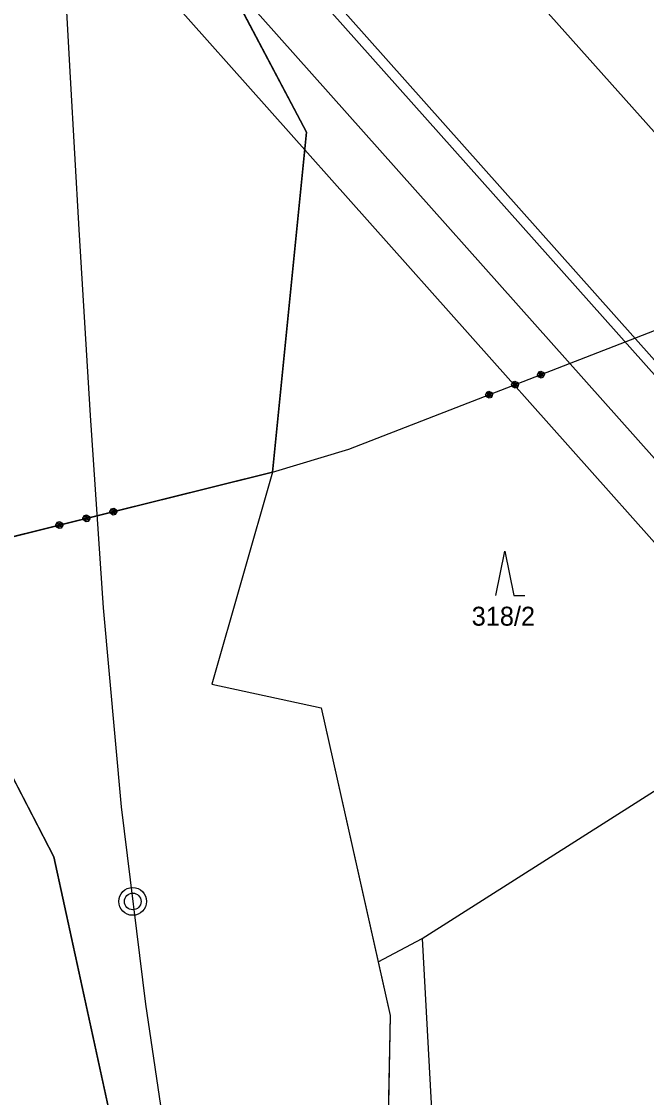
# Model space of a CAD drawing. Extents: x -866656 to -858817, y -1041816 to -1038653.
# Drawn here: x -865011.3 to -864955.2, y -1040747.1 to -1040650.5 of the extents above; entities that cross this region are included whole.
import ezdxf

# ---------------------------------------------------------------- set-up
doc = ezdxf.new("R2010")
doc.units = 0
for name, color, linetype in [('SZDC', 7, 'Continuous'), ('tisk ramy', 7, 'Continuous'), ('Vrstva 1', 7, 'Continuous'), ('Vrstva 3', 7, 'Continuous'), ('Vrstva 53', 7, 'Continuous'), ('Vrstva 7', 7, 'Continuous')]:
    doc.layers.add(name, color=color, linetype=linetype)

msp = doc.modelspace()

# ---------------------------------------------------------------- linework, layer by layer
at = {"layer": 'SZDC'}
for points in [[(-865001.396, -1040539.962), (-864993.688, -1040579.203), (-864996.501, -1040608.857), (-865002.06, -1040629.39), (-864985.688, -1040660.423), (-864988.738, -1040690.926), (-865021.96, -1040699.19), (-865027.168, -1040689.139), (-865033.06, -1040677.767), (-865026.63, -1040662), (-865024.654, -1040657.157), (-865013.46, -1040629.71), (-865015.641, -1040623.593), (-865021.207, -1040607.979), (-865022.973, -1040591.404), (-865024.6, -1040576.14), (-865021.44, -1040540.27)], [(-864972.331, -1040948.544), (-864965.463, -1040904.572), (-864985, -1040866.09), (-864987.66, -1040820.56), (-865008.38, -1040725.45), (-865021.96, -1040699.19), (-864988.738, -1040690.926), (-864994.191, -1040709.967), (-864984.36, -1040712.09), (-864979.245, -1040734.883), (-864978.161, -1040739.712), (-864978.755, -1040767.78), (-864956.64, -1040823.78), (-864971.416, -1040839.192), (-864953.61, -1040862.72), (-864958.96, -1040864.07), (-864953.81, -1040886.99), (-864953.18, -1040911.04), (-864934.86, -1040933.14), (-864931.196, -1040972.036)]]:
    msp.add_lwpolyline(points, dxfattribs=at)
at = {"layer": 'tisk ramy'}
for p, q in [((-865006.182, -1040602.312), (-864942.746, -1040673.565)), ((-864896.72, -1040747.042), (-865017.586, -1040611.282)), ((-865016.338, -1040611.354), (-864952.902, -1040682.607))]:
    msp.add_line(p, q, dxfattribs=at)
for points in [[(-865732.632, -1039823.163), (-864894.802, -1040764.235), (-864672.984, -1040566.751), (-865510.814, -1039625.68)], [(-865511.224, -1039632.739), (-864680.043, -1040566.341), (-864894.393, -1040757.175), (-865725.573, -1039823.573)]]:
    msp.add_lwpolyline(points, close=True, dxfattribs=at)
at = {"layer": 'Vrstva 1'}
for p, q in [((-864985.688, -1040660.423), (-865002.06, -1040629.39)), ((-864988.738, -1040690.926), (-864985.688, -1040660.423)), ((-864988.738, -1040690.926), (-864994.191, -1040709.967)), ((-864968.68, -1040702.01), (-864967.88, -1040698.01)), ((-864967.88, -1040698.01), (-864967.08, -1040702.01)), ((-865021.96, -1040699.19), (-865008.38, -1040725.45)), ((-864967.08, -1040702.01), (-864966.08, -1040702.01)), ((-864994.191, -1040709.967), (-864984.36, -1040712.09)), ((-864984.36, -1040712.09), (-864978.161, -1040739.712)), ((-864975.3, -1040732.8), (-864945.5, -1040713.85)), ((-865008.38, -1040725.45), (-864987.66, -1040820.56)), ((-864979.245, -1040734.883), (-864975.3, -1040732.8)), ((-864975.3, -1040732.8), (-864973.89, -1040758.79)), ((-864978.161, -1040739.712), (-864978.755, -1040767.78))]:
    msp.add_line(p, q, dxfattribs=at)
for points in [[(-865018.381, -1040455.781), (-865018.108, -1040460.39), (-865017.217, -1040475.753), (-865015.827, -1040499.871), (-865013.524, -1040539.806), (-865010.906, -1040584.551), (-865008.335, -1040629.672), (-865006.896, -1040655.504), (-865006.134, -1040669.149), (-865005.12, -1040685.843), (-865003.949, -1040703.111)], [(-865003.949, -1040703.111), (-865002.333, -1040720.961), (-865000.151, -1040738.69), (-864998.444, -1040750.203), (-864996.845, -1040759.743), (-864995.021, -1040769.634), (-864993.251, -1040778.494), (-864990.899, -1040789.361), (-864988.534, -1040799.208), (-864982.898, -1040820.532)]]:
    msp.add_lwpolyline(points, dxfattribs=at)
at = {"layer": 'Vrstva 3'}
for p, q in [((-864981.88, -1040688.87), (-864951.85, -1040677.21)), ((-864981.88, -1040688.87), (-864951.85, -1040677.21)), ((-864964.943, -1040682.186), (-864964.829, -1040681.927)), ((-864964.943, -1040682.186), (-864964.829, -1040681.927)), ((-864964.829, -1040681.927), (-864964.643, -1040681.855)), ((-864964.829, -1040681.927), (-864964.643, -1040681.855)), ((-864964.793, -1040682.021), (-864964.606, -1040681.948)), ((-864964.793, -1040682.021), (-864964.606, -1040681.948)), ((-864964.648, -1040682.393), (-864964.793, -1040682.021)), ((-864964.648, -1040682.393), (-864964.793, -1040682.021)), ((-864964.7, -1040681.984), (-864964.555, -1040682.357)), ((-864964.7, -1040681.984), (-864964.555, -1040682.357)), ((-864964.643, -1040681.855), (-864964.384, -1040681.969)), ((-864964.643, -1040681.855), (-864964.384, -1040681.969)), ((-864964.606, -1040681.948), (-864964.462, -1040682.321)), ((-864964.606, -1040681.948), (-864964.462, -1040682.321)), ((-864964.405, -1040682.192), (-864964.477, -1040682.005)), ((-864964.405, -1040682.192), (-864964.477, -1040682.005)), ((-864964.384, -1040681.969), (-864964.311, -1040682.155)), ((-864964.384, -1040681.969), (-864964.311, -1040682.155)), ((-864967.274, -1040683.091), (-864967.16, -1040682.832)), ((-864967.274, -1040683.091), (-864967.16, -1040682.832)), ((-864967.201, -1040683.278), (-864967.274, -1040683.091)), ((-864967.201, -1040683.278), (-864967.274, -1040683.091)), ((-864967.18, -1040683.055), (-864967.108, -1040683.241)), ((-864967.18, -1040683.055), (-864967.108, -1040683.241)), ((-864967.16, -1040682.832), (-864966.973, -1040682.76)), ((-864967.16, -1040682.832), (-864966.973, -1040682.76)), ((-864967.123, -1040682.925), (-864966.937, -1040682.853)), ((-864967.123, -1040682.925), (-864966.937, -1040682.853)), ((-864966.979, -1040683.298), (-864967.123, -1040682.925)), ((-864966.979, -1040683.298), (-864967.123, -1040682.925)), ((-864967.03, -1040682.889), (-864966.885, -1040683.262)), ((-864967.03, -1040682.889), (-864966.885, -1040683.262)), ((-864966.973, -1040682.76), (-864966.714, -1040682.874)), ((-864966.973, -1040682.76), (-864966.714, -1040682.874)), ((-864966.937, -1040682.853), (-864966.792, -1040683.226)), ((-864966.937, -1040682.853), (-864966.792, -1040683.226)), ((-864966.735, -1040683.097), (-864966.807, -1040682.91)), ((-864966.735, -1040683.097), (-864966.807, -1040682.91)), ((-864966.642, -1040683.06), (-864966.756, -1040683.319)), ((-864966.642, -1040683.06), (-864966.756, -1040683.319)), ((-864966.714, -1040682.874), (-864966.642, -1040683.06)), ((-864966.714, -1040682.874), (-864966.642, -1040683.06)), ((-864964.871, -1040682.373), (-864964.943, -1040682.186)), ((-864964.871, -1040682.373), (-864964.943, -1040682.186)), ((-864964.612, -1040682.487), (-864964.871, -1040682.373)), ((-864964.612, -1040682.487), (-864964.871, -1040682.373)), ((-864964.85, -1040682.15), (-864964.777, -1040682.336)), ((-864964.85, -1040682.15), (-864964.777, -1040682.336)), ((-864964.777, -1040682.336), (-864964.648, -1040682.393)), ((-864964.777, -1040682.336), (-864964.648, -1040682.393)), ((-864964.425, -1040682.414), (-864964.612, -1040682.487)), ((-864964.425, -1040682.414), (-864964.612, -1040682.487)), ((-864964.462, -1040682.321), (-864964.405, -1040682.192)), ((-864964.462, -1040682.321), (-864964.405, -1040682.192)), ((-864964.311, -1040682.155), (-864964.425, -1040682.414)), ((-864964.311, -1040682.155), (-864964.425, -1040682.414)), ((-864969.604, -1040683.996), (-864969.49, -1040683.737)), ((-864969.604, -1040683.996), (-864969.49, -1040683.737)), ((-864969.532, -1040684.182), (-864969.604, -1040683.996)), ((-864969.532, -1040684.182), (-864969.604, -1040683.996)), ((-864969.511, -1040683.96), (-864969.438, -1040684.146)), ((-864969.511, -1040683.96), (-864969.438, -1040684.146)), ((-864969.49, -1040683.737), (-864969.304, -1040683.665)), ((-864969.49, -1040683.737), (-864969.304, -1040683.665)), ((-864969.454, -1040683.83), (-864969.267, -1040683.758)), ((-864969.454, -1040683.83), (-864969.267, -1040683.758)), ((-864969.309, -1040684.203), (-864969.454, -1040683.83)), ((-864969.309, -1040684.203), (-864969.454, -1040683.83)), ((-864969.361, -1040683.794), (-864969.216, -1040684.167)), ((-864969.361, -1040683.794), (-864969.216, -1040684.167)), ((-864969.304, -1040683.665), (-864969.045, -1040683.779)), ((-864969.304, -1040683.665), (-864969.045, -1040683.779)), ((-864969.267, -1040683.758), (-864969.123, -1040684.131)), ((-864969.267, -1040683.758), (-864969.123, -1040684.131)), ((-864969.066, -1040684.001), (-864969.138, -1040683.815)), ((-864969.066, -1040684.001), (-864969.138, -1040683.815)), ((-864969.123, -1040684.131), (-864969.066, -1040684.001)), ((-864969.123, -1040684.131), (-864969.066, -1040684.001)), ((-864968.972, -1040683.965), (-864969.086, -1040684.224)), ((-864968.972, -1040683.965), (-864969.086, -1040684.224)), ((-864969.045, -1040683.779), (-864968.972, -1040683.965)), ((-864969.045, -1040683.779), (-864968.972, -1040683.965)), ((-864966.942, -1040683.392), (-864967.201, -1040683.278)), ((-864966.942, -1040683.392), (-864967.201, -1040683.278)), ((-864967.108, -1040683.241), (-864966.979, -1040683.298)), ((-864967.108, -1040683.241), (-864966.979, -1040683.298)), ((-864966.756, -1040683.319), (-864966.942, -1040683.392)), ((-864966.756, -1040683.319), (-864966.942, -1040683.392)), ((-864966.792, -1040683.226), (-864966.735, -1040683.097)), ((-864966.792, -1040683.226), (-864966.735, -1040683.097)), ((-864969.273, -1040684.296), (-864969.532, -1040684.182)), ((-864969.273, -1040684.296), (-864969.532, -1040684.182)), ((-864969.438, -1040684.146), (-864969.309, -1040684.203)), ((-864969.438, -1040684.146), (-864969.309, -1040684.203)), ((-864969.086, -1040684.224), (-864969.273, -1040684.296)), ((-864969.086, -1040684.224), (-864969.273, -1040684.296)), ((-864988.738, -1040690.926), (-864981.88, -1040688.87)), ((-864988.738, -1040690.926), (-864981.88, -1040688.87)), ((-865021.96, -1040699.19), (-864988.738, -1040690.926)), ((-864988.738, -1040690.926), (-865021.96, -1040699.19)), ((-865003.335, -1040694.454), (-865003.189, -1040694.211)), ((-865003.335, -1040694.454), (-865003.189, -1040694.211)), ((-865003.287, -1040694.648), (-865003.335, -1040694.454)), ((-865003.287, -1040694.648), (-865003.335, -1040694.454)), ((-865003.044, -1040694.794), (-865003.287, -1040694.648)), ((-865003.044, -1040694.794), (-865003.287, -1040694.648)), ((-865003.238, -1040694.43), (-865003.19, -1040694.624)), ((-865003.238, -1040694.43), (-865003.19, -1040694.624)), ((-865003.19, -1040694.624), (-865003.069, -1040694.696)), ((-865003.19, -1040694.624), (-865003.069, -1040694.696)), ((-865003.189, -1040694.211), (-865002.995, -1040694.163)), ((-865003.189, -1040694.211), (-865002.995, -1040694.163)), ((-865003.165, -1040694.308), (-865002.971, -1040694.26)), ((-865003.165, -1040694.308), (-865002.971, -1040694.26)), ((-865003.069, -1040694.696), (-865003.165, -1040694.308)), ((-865003.069, -1040694.696), (-865003.165, -1040694.308)), ((-865003.068, -1040694.284), (-865002.971, -1040694.672)), ((-865003.068, -1040694.284), (-865002.971, -1040694.672)), ((-865002.995, -1040694.163), (-865002.753, -1040694.309)), ((-865002.995, -1040694.163), (-865002.753, -1040694.309)), ((-865002.971, -1040694.26), (-865002.874, -1040694.648)), ((-865002.971, -1040694.26), (-865002.874, -1040694.648)), ((-865002.874, -1040694.648), (-865002.802, -1040694.527)), ((-865002.874, -1040694.648), (-865002.802, -1040694.527)), ((-865002.802, -1040694.527), (-865002.85, -1040694.333)), ((-865002.802, -1040694.527), (-865002.85, -1040694.333)), ((-865002.704, -1040694.503), (-865002.85, -1040694.745)), ((-865002.704, -1040694.503), (-865002.85, -1040694.745)), ((-865002.753, -1040694.309), (-865002.704, -1040694.503)), ((-865002.753, -1040694.309), (-865002.704, -1040694.503)), ((-865008.187, -1040695.661), (-865008.041, -1040695.418)), ((-865008.187, -1040695.661), (-865008.041, -1040695.418)), ((-865008.09, -1040695.636), (-865008.042, -1040695.831)), ((-865008.09, -1040695.636), (-865008.042, -1040695.831)), ((-865008.041, -1040695.418), (-865007.847, -1040695.37)), ((-865008.041, -1040695.418), (-865007.847, -1040695.37)), ((-865008.017, -1040695.515), (-865007.823, -1040695.467)), ((-865008.017, -1040695.515), (-865007.823, -1040695.467)), ((-865007.921, -1040695.903), (-865008.017, -1040695.515)), ((-865007.921, -1040695.903), (-865008.017, -1040695.515)), ((-865007.92, -1040695.491), (-865007.824, -1040695.879)), ((-865007.92, -1040695.491), (-865007.824, -1040695.879)), ((-865007.847, -1040695.37), (-865007.605, -1040695.516)), ((-865007.847, -1040695.37), (-865007.605, -1040695.516)), ((-865007.823, -1040695.467), (-865007.727, -1040695.855)), ((-865007.823, -1040695.467), (-865007.727, -1040695.855)), ((-865007.654, -1040695.734), (-865007.702, -1040695.54)), ((-865007.654, -1040695.734), (-865007.702, -1040695.54)), ((-865007.605, -1040695.516), (-865007.557, -1040695.71)), ((-865007.605, -1040695.516), (-865007.557, -1040695.71)), ((-865005.761, -1040695.057), (-865005.615, -1040694.815)), ((-865005.761, -1040695.057), (-865005.615, -1040694.815)), ((-865005.713, -1040695.251), (-865005.761, -1040695.057)), ((-865005.713, -1040695.251), (-865005.761, -1040695.057)), ((-865005.47, -1040695.397), (-865005.713, -1040695.251)), ((-865005.47, -1040695.397), (-865005.713, -1040695.251)), ((-865005.664, -1040695.033), (-865005.616, -1040695.227)), ((-865005.664, -1040695.033), (-865005.616, -1040695.227)), ((-865005.616, -1040695.227), (-865005.495, -1040695.3)), ((-865005.616, -1040695.227), (-865005.495, -1040695.3)), ((-865005.615, -1040694.815), (-865005.421, -1040694.766)), ((-865005.615, -1040694.815), (-865005.421, -1040694.766)), ((-865005.591, -1040694.912), (-865005.397, -1040694.864)), ((-865005.591, -1040694.912), (-865005.397, -1040694.864)), ((-865005.495, -1040695.3), (-865005.591, -1040694.912)), ((-865005.495, -1040695.3), (-865005.591, -1040694.912)), ((-865005.494, -1040694.888), (-865005.398, -1040695.276)), ((-865005.494, -1040694.888), (-865005.398, -1040695.276)), ((-865005.276, -1040695.349), (-865005.47, -1040695.397)), ((-865005.276, -1040695.349), (-865005.47, -1040695.397)), ((-865005.421, -1040694.766), (-865005.179, -1040694.912)), ((-865005.421, -1040694.766), (-865005.179, -1040694.912)), ((-865005.397, -1040694.864), (-865005.301, -1040695.252)), ((-865005.397, -1040694.864), (-865005.301, -1040695.252)), ((-865005.301, -1040695.252), (-865005.228, -1040695.131)), ((-865005.301, -1040695.252), (-865005.228, -1040695.131)), ((-865005.228, -1040695.131), (-865005.276, -1040694.936)), ((-865005.228, -1040695.131), (-865005.276, -1040694.936)), ((-865005.131, -1040695.106), (-865005.276, -1040695.349)), ((-865005.131, -1040695.106), (-865005.276, -1040695.349)), ((-865005.179, -1040694.912), (-865005.131, -1040695.106)), ((-865005.179, -1040694.912), (-865005.131, -1040695.106)), ((-865002.85, -1040694.745), (-865003.044, -1040694.794)), ((-865002.85, -1040694.745), (-865003.044, -1040694.794)), ((-865008.139, -1040695.855), (-865008.187, -1040695.661)), ((-865008.139, -1040695.855), (-865008.187, -1040695.661)), ((-865007.897, -1040696), (-865008.139, -1040695.855)), ((-865007.897, -1040696), (-865008.139, -1040695.855)), ((-865008.042, -1040695.831), (-865007.921, -1040695.903)), ((-865008.042, -1040695.831), (-865007.921, -1040695.903)), ((-865007.702, -1040695.952), (-865007.897, -1040696)), ((-865007.702, -1040695.952), (-865007.897, -1040696)), ((-865007.727, -1040695.855), (-865007.654, -1040695.734)), ((-865007.727, -1040695.855), (-865007.654, -1040695.734)), ((-865007.557, -1040695.71), (-865007.702, -1040695.952)), ((-865007.557, -1040695.71), (-865007.702, -1040695.952))]:
    msp.add_line(p, q, dxfattribs=at)
at = {"layer": 'Vrstva 53'}
for points in [[(-865023.67, -1040361.98), (-865022.71, -1040375.04), (-865013.7, -1040387.94), (-865007.96, -1040405.65), (-865004.28, -1040432.65), (-865006.72, -1040446.26), (-865008.54, -1040457.65), (-865009.56, -1040462.703), (-864989.06, -1040471.31), (-864982.509, -1040497.573), (-865001.396, -1040539.962), (-864993.688, -1040579.203), (-864996.501, -1040608.857), (-865002.06, -1040629.39), (-864985.688, -1040660.423), (-864988.738, -1040690.926)], [(-864988.738, -1040690.926), (-864994.191, -1040709.968), (-864984.36, -1040712.091), (-864979.245, -1040734.883), (-864978.161, -1040739.713), (-864978.755, -1040767.781), (-864956.64, -1040823.781), (-864971.416, -1040839.193), (-864953.61, -1040862.721), (-864958.96, -1040864.071), (-864953.81, -1040886.991), (-864953.18, -1040911.041), (-864934.86, -1040933.141), (-864931.196, -1040972.037)], [(-864972.331, -1040948.545), (-864965.463, -1040904.573), (-864985, -1040866.091), (-864987.66, -1040820.561), (-865008.38, -1040725.451), (-865021.96, -1040699.19)]]:
    msp.add_lwpolyline(points, dxfattribs=at)
at = {"layer": 'Vrstva 7'}
for radius in [1.246, 0.752]:
    msp.add_circle((-865001.286, -1040729.465), radius, dxfattribs=at)

# ---------------------------------------------------------------- texts
at = {"layer": 'Vrstva 1'}
msp.add_text('318/2', height=1.7, dxfattribs=at).set_placement((-864970.853, -1040704.71))

doc.saveas('drawing.dxf')
